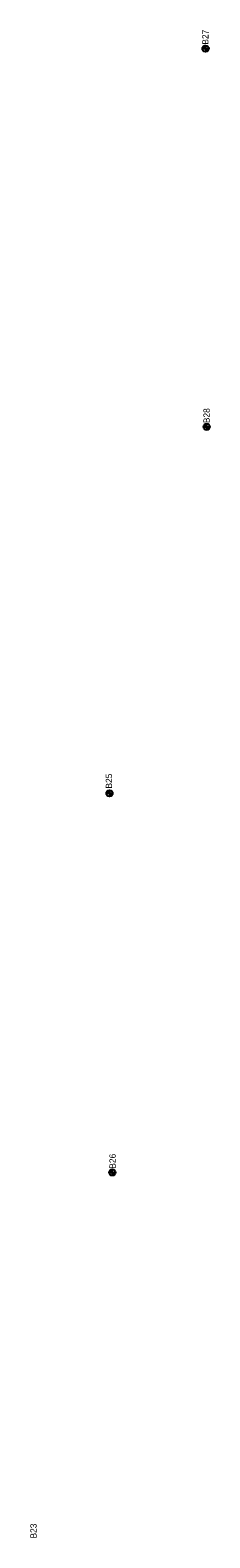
# Model space of a CAD drawing. Extents: x 311409 to 379449, y 121539 to 224848.
# Drawn here: x 361587 to 361873, y 141549 to 143954 of the extents above; entities that cross this region are included whole.
import ezdxf

# ---------------------------------------------------------------- set-up
doc = ezdxf.new("R2010")
doc.units = 0
for name, color, linetype in [('E_SOIL_BORE1 [KAPUR_CADDS_LEVELS]', 7, 'Continuous'), ('E_SOIL_BORE2 [KAPUR_CADDS_LEVELS]', 7, 'Continuous'), ('P_MARK', 7, 'Continuous')]:
    doc.layers.add(name, color=color, linetype=linetype)

msp = doc.modelspace()

# ---------------------------------------------------------------- linework, layer by layer
at = {"layer": 'P_MARK'}
for p, q in [((361861.3, 143924.9), (361871.3, 143924.9)), ((361866.3, 143929.9), (361866.3, 143919.9)), ((361863, 143321.3), (361873, 143321.3)), ((361868, 143326.3), (361868, 143316.3)), ((361708.4, 142736.6), (361718.4, 142736.6)), ((361713.4, 142741.6), (361713.4, 142731.6)), ((361712.8, 142131.6), (361722.8, 142131.6)), ((361717.8, 142136.6), (361717.8, 142126.6))]:
    msp.add_line(p, q, dxfattribs=at)
for centre in [(361866.3, 143924.9), (361868, 143321.3), (361713.4, 142736.6), (361717.8, 142131.6)]:
    msp.add_circle(centre, 5, dxfattribs=at)
for centre, radius, start, end in [((361866.3, 143924.9), 4.5, 89.9869, 179.9869), ((361866.3, 143924.9), 4, 89.9869, 179.9869), ((361866.3, 143924.9), 3.5, 89.9869, 179.9869), ((361866.3, 143924.9), 3, 89.9869, 179.9869), ((361866.3, 143924.9), 2.5, 89.9869, 179.9869), ((361866.3, 143924.9), 2, 89.9869, 179.9869), ((361866.3, 143924.9), 1.5, 89.9869, 179.9869), ((361866.3, 143924.9), 1, 89.9869, 179.9869), ((361866.3, 143924.9), 0.5, 89.9869, 179.9869), ((361866.3, 143924.9), 4.5, 269.9869, 359.9869), ((361866.3, 143924.9), 4, 269.9869, 359.9869), ((361866.3, 143924.9), 3.5, 269.9869, 359.9869), ((361866.3, 143924.9), 3, 269.9869, 359.9869), ((361866.3, 143924.9), 2.5, 269.9869, 359.9869), ((361866.3, 143924.9), 2, 269.9869, 359.9869), ((361866.3, 143924.9), 1.5, 269.9869, 359.9869), ((361866.3, 143924.9), 1, 269.9869, 359.9869), ((361866.3, 143924.9), 0.5, 269.9869, 359.9869), ((361868, 143321.3), 4.5, 89.9869, 179.9869), ((361868, 143321.3), 4, 89.9869, 179.9869), ((361868, 143321.3), 3.5, 89.9869, 179.9869), ((361868, 143321.3), 3, 89.9869, 179.9869), ((361868, 143321.3), 2.5, 89.9869, 179.9869), ((361868, 143321.3), 2, 89.9869, 179.9869), ((361868, 143321.3), 1.5, 89.9869, 179.9869), ((361868, 143321.3), 1, 89.9869, 179.9869), ((361868, 143321.3), 0.5, 89.9869, 179.9869), ((361868, 143321.3), 4.5, 269.9869, 359.9869), ((361868, 143321.3), 4, 269.9869, 359.9869), ((361868, 143321.3), 3.5, 269.9869, 359.9869), ((361868, 143321.3), 3, 269.9869, 359.9869), ((361868, 143321.3), 2.5, 269.9869, 359.9869), ((361868, 143321.3), 2, 269.9869, 359.9869), ((361868, 143321.3), 1.5, 269.9869, 359.9869), ((361868, 143321.3), 1, 269.9869, 359.9869), ((361868, 143321.3), 0.5, 269.9869, 359.9869), ((361713.4, 142736.6), 4.5, 89.9869, 179.9869), ((361713.4, 142736.6), 4, 89.9869, 179.9869), ((361713.4, 142736.6), 3.5, 89.9869, 179.9869), ((361713.4, 142736.6), 3, 89.9869, 179.9869), ((361713.4, 142736.6), 2.5, 89.9869, 179.9869), ((361713.4, 142736.6), 2, 89.9869, 179.9869), ((361713.4, 142736.6), 1.5, 89.9869, 179.9869), ((361713.4, 142736.6), 1, 89.9869, 179.9869), ((361713.4, 142736.6), 0.5, 89.9869, 179.9869), ((361713.4, 142736.6), 4.5, 269.9869, 359.9869), ((361713.4, 142736.6), 4, 269.9869, 359.9869), ((361713.4, 142736.6), 3.5, 269.9869, 359.9869), ((361713.4, 142736.6), 3, 269.9869, 359.9869), ((361713.4, 142736.6), 2.5, 269.9869, 359.9869), ((361713.4, 142736.6), 2, 269.9869, 359.9869), ((361713.4, 142736.6), 1.5, 269.9869, 359.9869), ((361713.4, 142736.6), 1, 269.9869, 359.9869), ((361713.4, 142736.6), 0.5, 269.9869, 359.9869), ((361717.8, 142131.6), 4.5, 89.9869, 179.9869), ((361717.8, 142131.6), 4, 89.9869, 179.9869), ((361717.8, 142131.6), 3.5, 89.9869, 179.9869), ((361717.8, 142131.6), 3, 89.9869, 179.9869), ((361717.8, 142131.6), 2.5, 89.9869, 179.9869), ((361717.8, 142131.6), 2, 89.9869, 179.9869), ((361717.8, 142131.6), 1.5, 89.9869, 179.9869), ((361717.8, 142131.6), 1, 89.9869, 179.9869), ((361717.8, 142131.6), 0.5, 89.9869, 179.9869), ((361717.8, 142131.6), 4.5, 269.9869, 359.9869), ((361717.8, 142131.6), 4, 269.9869, 359.9869), ((361717.8, 142131.6), 3.5, 269.9869, 359.9869), ((361717.8, 142131.6), 3, 269.9869, 359.9869), ((361717.8, 142131.6), 2.5, 269.9869, 359.9869), ((361717.8, 142131.6), 2, 269.9869, 359.9869), ((361717.8, 142131.6), 1.5, 269.9869, 359.9869), ((361717.8, 142131.6), 1, 269.9869, 359.9869), ((361717.8, 142131.6), 0.5, 269.9869, 359.9869)]:
    msp.add_arc(centre, radius, start, end, dxfattribs=at)

# ---------------------------------------------------------------- texts
at = {"layer": 'E_SOIL_BORE1 [KAPUR_CADDS_LEVELS]'}
for s, p in [('B27', (361871, 143931.2)), ('B23', (361597.4, 141547.5))]:
    msp.add_text(s, height=10, rotation=89.9869, dxfattribs=at).set_placement(p)
at = {"layer": 'E_SOIL_BORE2 [KAPUR_CADDS_LEVELS]'}
for s, p in [('B28', (361872.9, 143327.2)), ('B25', (361717.5, 142744.2)), ('B26', (361723.3, 142137.6))]:
    msp.add_text(s, height=10, rotation=89.9869, dxfattribs=at).set_placement(p)

doc.saveas('drawing.dxf')
